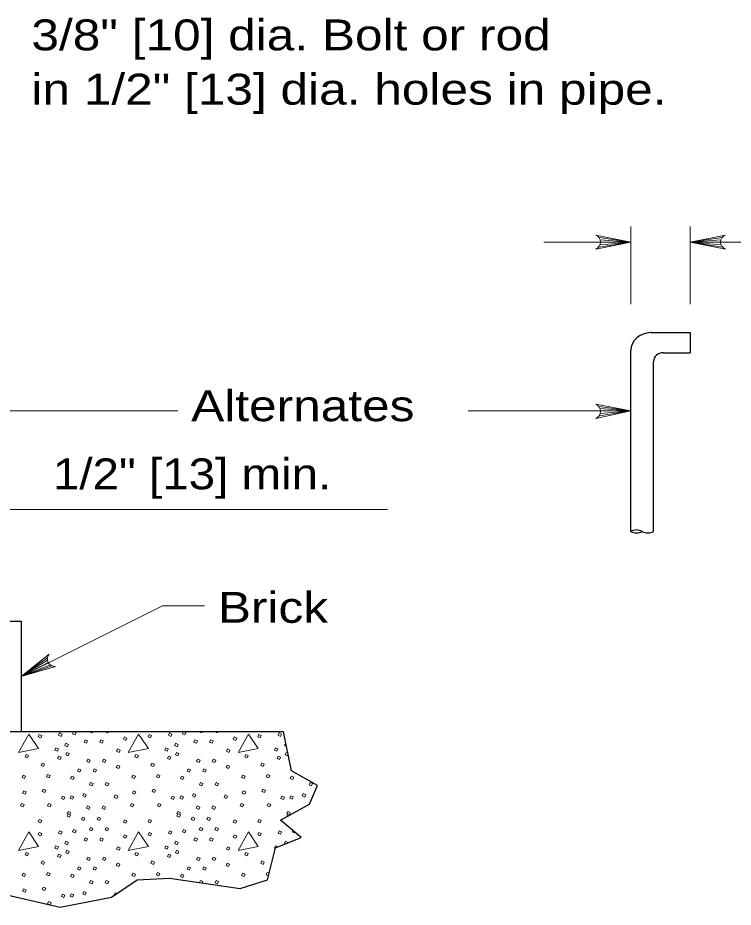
# Model space of a CAD drawing. Extents: x 1083.1 to 1117.1, y 697.4 to 741.4.
# Drawn here: x 1105.026 to 1108.637, y 729.063 to 733.552 of the extents above; entities that cross this region are included whole.
import ezdxf

# ---------------------------------------------------------------- set-up
doc = ezdxf.new("R2010")
doc.units = 0
doc.header["$LTSCALE"] = 0.062
doc.layers.add('1', color=7, linetype='Continuous', lineweight=13)

msp = doc.modelspace()

# ---------------------------------------------------------------- linework, layer by layer
at = {"layer": '1'}
for p, q in [((1108.12092, 732.10692), (1108.12092, 732.49875)), ((1108.42075, 732.10692), (1108.42075, 732.49875)), ((1107.68142, 732.42008), (1108.12092, 732.42008)), ((1107.95875, 732.39525), (1108.12092, 732.42008)), ((1107.96067, 732.4425), (1108.12092, 732.42008)), ((1107.96492, 732.40567), (1108.12092, 732.42008)), ((1107.96608, 732.43142), (1108.12092, 732.42008)), ((1107.96775, 732.42008), (1108.12092, 732.42008)), ((1108.581, 732.4425), (1108.42075, 732.42008)), ((1108.57558, 732.43142), (1108.42075, 732.42008)), ((1108.42075, 732.42008), (1109.891, 732.42008)), ((1108.57392, 732.42008), (1108.42075, 732.42008)), ((1108.57675, 732.40567), (1108.42075, 732.42008)), ((1108.58292, 732.39525), (1108.42075, 732.42008)), ((1108.22083, 731.963), (1108.22208, 731.963)), ((1104.49667, 731.56783), (1105.834, 731.56783)), ((1107.29892, 731.56783), (1108.12092, 731.56783)), ((1107.9585, 731.59092), (1108.12092, 731.56783)), ((1107.96092, 731.54375), (1108.12092, 731.56783)), ((1107.96475, 731.58058), (1108.12092, 731.56783)), ((1107.96625, 731.55492), (1108.12092, 731.56783)), ((1107.96775, 731.56625), (1108.12092, 731.56783)), ((1104.90975, 731.07075), (1106.89125, 731.07075)), ((1105.175, 730.32192), (1105.04333, 730.22792)), ((1105.17533, 730.30958), (1105.04333, 730.22792)), ((1105.17908, 730.29875), (1105.04333, 730.22792)), ((1105.18825, 730.28733), (1105.04333, 730.22792)), ((1105.1985, 730.28092), (1105.04333, 730.22792)), ((1106.377, 729.89042), (1106.37958, 729.88925)), ((1106.38125, 729.84483), (1106.38958, 729.84125)), ((1105.27467, 729.53533), (1105.27967, 729.54675)), ((1105.829, 729.53533), (1105.834, 729.54675)), ((1106.38333, 729.53533), (1106.38833, 729.54675)), ((1106.32667, 729.37325), (1106.33883, 729.368)), ((1106.285, 729.23917), (1106.29475, 729.23492)), ((1105.94275, 729.18775), (1105.94733, 729.19808)), ((1105.51267, 729.12408), (1105.5175, 729.13517)), ((1105.5175, 729.13517), (1105.52458, 729.13208))]:
    msp.add_line(p, q, dxfattribs=at)
at = {"layer": '1', "lineweight": 25}
for p, q in [((1108.22083, 731.963), (1108.42075, 731.963)), ((1108.42075, 731.963), (1108.42075, 731.86183)), ((1108.12092, 730.95983), (1108.12092, 731.87308)), ((1108.28508, 731.86183), (1108.42075, 731.86183)), ((1108.23517, 730.95983), (1108.23517, 731.81683)), ((1105.04333, 730.50717), (1105.04333, 729.94858))]:
    msp.add_line(p, q, dxfattribs=at)
at = {"layer": '1'}
for points in [[(1107.94392, 732.38467), (1108.12092, 732.42008), (1107.94392, 732.45542)], [(1108.59775, 732.38467), (1108.42075, 732.42008), (1108.59775, 732.45542)], [(1107.9435, 731.60142), (1108.12092, 731.56783), (1107.94425, 731.53058)], [(1105.04333, 730.22792), (1105.75608, 730.58458), (1105.9685, 730.58458)], [(1105.21658, 730.27842), (1105.04333, 730.22792), (1105.18383, 730.34117)], [(1105.31017, 729.94858), (1105.31983, 729.94442), (1105.31467, 729.93258), (1105.30217, 729.938), (1105.30683, 729.94858)], [(1105.40233, 729.94858), (1105.39967, 729.9425), (1105.38717, 729.94792), (1105.38742, 729.94858)], [(1105.4815, 729.94858), (1105.47883, 729.9425), (1105.46633, 729.94792), (1105.46667, 729.94858)], [(1105.8645, 729.94858), (1105.87417, 729.94442), (1105.869, 729.93258), (1105.8565, 729.938), (1105.86117, 729.94858)], [(1105.95667, 729.94858), (1105.954, 729.9425), (1105.9415, 729.94792), (1105.94175, 729.94858)], [(1106.03583, 729.94858), (1106.03317, 729.9425), (1106.02067, 729.94792), (1106.021, 729.94858)], [(1106.38275, 729.87383), (1106.37183, 729.87858), (1106.377, 729.89042)], [(1106.39117, 729.8335), (1106.38858, 729.82758), (1106.37608, 729.833), (1106.38125, 729.84483)], [(1105.27967, 729.54675), (1105.29217, 729.54133), (1105.28958, 729.53533)], [(1105.834, 729.54675), (1105.8465, 729.54133), (1105.84392, 729.53533)], [(1106.38683, 729.52192), (1106.38317, 729.5235), (1106.38833, 729.53533)], [(1106.38833, 729.54675), (1106.40083, 729.54133), (1106.39825, 729.53533)], [(1106.38833, 729.53533), (1106.40083, 729.52992), (1106.40067, 729.5295)], [(1106.42467, 729.44133), (1106.42333, 729.43817), (1106.41083, 729.44358), (1106.41383, 729.45033)], [(1106.326, 729.3595), (1106.3215, 729.36142), (1106.32667, 729.37325)], [(1106.3755, 729.3825), (1106.37183, 729.38408), (1106.377, 729.39592)], [(1106.377, 729.39592), (1106.3895, 729.3905), (1106.38817, 729.3875)], [(1106.29158, 729.22225), (1106.27983, 729.22733), (1106.285, 729.23917)], [(1105.94733, 729.19808), (1105.95983, 729.19267), (1105.95675, 729.18575)]]:
    msp.add_lwpolyline(points, dxfattribs=at)
at = {"layer": '1', "lineweight": 25}
for points in [[(1102.06542, 730.50717), (1104.80275, 730.50717), (1105.04333, 730.50717)], [(1106.36717, 729.94858), (1100.89558, 729.94858), (1100.89692, 729.84967)], [(1104.95458, 729.12908), (1105.23883, 729.06325), (1105.4985, 729.1145), (1105.62867, 729.20225), (1105.79083, 729.2095), (1106.14833, 729.15825), (1106.2865, 729.20225), (1106.327, 729.36333), (1106.45683, 729.41458), (1106.35125, 729.50233), (1106.49758, 729.583), (1106.53808, 729.678), (1106.40825, 729.75133), (1106.36717, 729.94858)]]:
    msp.add_lwpolyline(points, dxfattribs=at)
at = {"layer": '1'}
for points in [[(1105.23658, 729.94275), (1105.24908, 729.93733), (1105.24392, 729.9255), (1105.23142, 729.93092)], [(1105.79092, 729.94275), (1105.80333, 729.93733), (1105.79817, 729.9255), (1105.78575, 729.93092)], [(1106.34517, 729.94275), (1106.35767, 729.93733), (1106.3525, 729.9255), (1106.34, 729.93092)], [(1105.081, 729.93733), (1105.02875, 729.84475), (1105.131, 729.86475)], [(1105.13383, 729.93492), (1105.14633, 729.9295), (1105.14117, 729.91767), (1105.12867, 729.92308)], [(1105.36542, 729.908), (1105.37792, 729.90258), (1105.37275, 729.89083), (1105.36025, 729.89625)], [(1105.44458, 729.908), (1105.45708, 729.90258), (1105.45192, 729.89083), (1105.43942, 729.89625)], [(1105.564, 729.92267), (1105.5765, 729.91725), (1105.57133, 729.90542), (1105.55883, 729.91083)], [(1105.63525, 729.93733), (1105.58308, 729.84475), (1105.68533, 729.86475)], [(1105.68817, 729.93492), (1105.70067, 729.9295), (1105.6955, 729.91767), (1105.683, 729.92308)], [(1105.91975, 729.908), (1105.93225, 729.90258), (1105.92708, 729.89083), (1105.91458, 729.89625)], [(1105.99892, 729.908), (1106.01142, 729.90258), (1106.00625, 729.89083), (1105.99375, 729.89625)], [(1106.11833, 729.92267), (1106.13083, 729.91725), (1106.12567, 729.90542), (1106.11317, 729.91083)], [(1106.18958, 729.93733), (1106.13742, 729.84475), (1106.23967, 729.86475)], [(1106.2425, 729.93492), (1106.255, 729.9295), (1106.24983, 729.91767), (1106.23733, 729.92308)], [(1105.21808, 729.86775), (1105.23058, 729.86233), (1105.22542, 729.8505), (1105.21292, 729.85592)], [(1105.26833, 729.89042), (1105.28083, 729.885), (1105.27567, 729.87317), (1105.26325, 729.87858)], [(1105.52958, 729.86208), (1105.54208, 729.85667), (1105.53692, 729.84483), (1105.52442, 729.85025)], [(1105.77242, 729.86775), (1105.78492, 729.86233), (1105.77975, 729.8505), (1105.76725, 729.85592)], [(1105.82267, 729.89042), (1105.83517, 729.885), (1105.83, 729.87317), (1105.8175, 729.87858)], [(1106.08392, 729.86208), (1106.09642, 729.85667), (1106.09125, 729.84483), (1106.07875, 729.85025)], [(1106.32667, 729.86775), (1106.33917, 729.86233), (1106.334, 729.8505), (1106.3215, 729.85592)], [(1105.068, 729.83417), (1105.0805, 729.82875), (1105.07533, 729.81692), (1105.06283, 729.82233)], [(1105.23158, 729.82567), (1105.24408, 729.82025), (1105.23892, 729.80842), (1105.22642, 729.81383)], [(1105.27258, 729.84483), (1105.28508, 729.83942), (1105.27992, 729.82758), (1105.26742, 729.833)], [(1105.37883, 729.81083), (1105.39133, 729.80542), (1105.38617, 729.79358), (1105.37367, 729.799)], [(1105.458, 729.81083), (1105.4705, 729.80542), (1105.46533, 729.79358), (1105.45283, 729.799)], [(1105.62225, 729.83417), (1105.63475, 729.82875), (1105.62958, 729.81692), (1105.61708, 729.82233)], [(1105.78592, 729.82567), (1105.79833, 729.82025), (1105.79325, 729.80842), (1105.78075, 729.81383)], [(1105.82692, 729.84483), (1105.83942, 729.83942), (1105.83425, 729.82758), (1105.82175, 729.833)], [(1105.93317, 729.81083), (1105.94567, 729.80542), (1105.9405, 729.79358), (1105.928, 729.799)], [(1106.01233, 729.81083), (1106.02483, 729.80542), (1106.01967, 729.79358), (1106.00717, 729.799)], [(1106.17658, 729.83417), (1106.18908, 729.82875), (1106.18392, 729.81692), (1106.17142, 729.82233)], [(1106.34017, 729.82567), (1106.35267, 729.82025), (1106.3475, 729.80842), (1106.335, 729.81383)], [(1105.14867, 729.791), (1105.16117, 729.78558), (1105.156, 729.77375), (1105.1435, 729.77917)], [(1105.33142, 729.76125), (1105.34392, 729.75583), (1105.33875, 729.74408), (1105.32625, 729.7495)], [(1105.41067, 729.76125), (1105.42317, 729.75583), (1105.418, 729.74408), (1105.4055, 729.7495)], [(1105.52817, 729.78033), (1105.54067, 729.77492), (1105.5355, 729.76308), (1105.523, 729.7685)], [(1105.703, 729.791), (1105.7155, 729.78558), (1105.71033, 729.77375), (1105.69783, 729.77917)], [(1105.88575, 729.76125), (1105.89825, 729.75583), (1105.89308, 729.74408), (1105.88058, 729.7495)], [(1105.965, 729.76125), (1105.97742, 729.75583), (1105.97225, 729.74408), (1105.95983, 729.7495)], [(1106.0825, 729.78033), (1106.095, 729.77492), (1106.08983, 729.76308), (1106.07733, 729.7685)], [(1106.25733, 729.791), (1106.26983, 729.78558), (1106.26467, 729.77375), (1106.25217, 729.77917)], [(1105.05242, 729.73017), (1105.06492, 729.72475), (1105.05975, 729.71292), (1105.04725, 729.71833)], [(1105.17633, 729.73367), (1105.18883, 729.72825), (1105.18367, 729.71642), (1105.17117, 729.72183)], [(1105.29742, 729.72517), (1105.30992, 729.71975), (1105.30475, 729.70792), (1105.29225, 729.71333)], [(1105.60675, 729.73017), (1105.61917, 729.72475), (1105.61408, 729.71292), (1105.60158, 729.71833)], [(1105.73067, 729.73367), (1105.74317, 729.72825), (1105.738, 729.71642), (1105.7255, 729.72183)], [(1105.85175, 729.72517), (1105.86425, 729.71975), (1105.85908, 729.70792), (1105.84658, 729.71333)], [(1106.161, 729.73017), (1106.1735, 729.72475), (1106.16833, 729.71292), (1106.15583, 729.71833)], [(1106.285, 729.73367), (1106.2975, 729.72825), (1106.29233, 729.71642), (1106.27983, 729.72183)], [(1106.40608, 729.72517), (1106.41858, 729.71975), (1106.41342, 729.70792), (1106.40092, 729.71333)], [(1105.393, 729.69258), (1105.4055, 729.68717), (1105.40033, 729.67533), (1105.38783, 729.68075)], [(1105.47217, 729.69258), (1105.48467, 729.68717), (1105.4795, 729.67533), (1105.467, 729.68075)], [(1105.94733, 729.69258), (1105.95983, 729.68717), (1105.95467, 729.67533), (1105.94217, 729.68075)], [(1106.0265, 729.69258), (1106.039, 729.68717), (1106.03383, 729.67533), (1106.02133, 729.68075)], [(1106.50158, 729.69258), (1106.51408, 729.68717), (1106.50892, 729.67533), (1106.4965, 729.68075)], [(1105.05533, 729.651), (1105.06783, 729.64558), (1105.06267, 729.63375), (1105.05017, 729.63917)], [(1105.15433, 729.65933), (1105.16683, 729.65392), (1105.16167, 729.64208), (1105.14917, 729.6475)], [(1105.25075, 729.62392), (1105.26325, 729.6185), (1105.25808, 729.60675), (1105.24558, 729.61208)], [(1105.29525, 729.626), (1105.30775, 729.62058), (1105.30258, 729.60883), (1105.29008, 729.61417)], [(1105.35833, 729.63667), (1105.37083, 729.63125), (1105.36567, 729.61942), (1105.35317, 729.62483)], [(1105.5175, 729.62958), (1105.53, 729.62417), (1105.52483, 729.61242), (1105.51233, 729.61775)], [(1105.60967, 729.651), (1105.62208, 729.64558), (1105.61692, 729.63375), (1105.6045, 729.63917)], [(1105.70867, 729.65933), (1105.72117, 729.65392), (1105.716, 729.64208), (1105.7035, 729.6475)], [(1105.805, 729.62392), (1105.8175, 729.6185), (1105.81233, 729.60675), (1105.79983, 729.61208)], [(1105.84958, 729.626), (1105.86208, 729.62058), (1105.85692, 729.60883), (1105.84442, 729.61417)], [(1105.91267, 729.63667), (1105.92517, 729.63125), (1105.92, 729.61942), (1105.9075, 729.62483)], [(1106.07183, 729.62958), (1106.08433, 729.62417), (1106.07917, 729.61242), (1106.06667, 729.61775)], [(1106.16392, 729.651), (1106.17642, 729.64558), (1106.17125, 729.63375), (1106.15875, 729.63917)], [(1106.263, 729.65933), (1106.2755, 729.65392), (1106.27033, 729.64208), (1106.25783, 729.6475)], [(1106.35933, 729.62392), (1106.37183, 729.6185), (1106.36667, 729.60675), (1106.35417, 729.61208)], [(1106.40392, 729.626), (1106.41642, 729.62058), (1106.41125, 729.60883), (1106.39875, 729.61417)], [(1106.467, 729.63667), (1106.4795, 729.63125), (1106.47433, 729.61942), (1106.46183, 729.62483)], [(1105.04492, 729.58692), (1105.05742, 729.5815), (1105.05225, 729.56967), (1105.03975, 729.57508)], [(1105.18125, 729.58717), (1105.19375, 729.58175), (1105.18858, 729.56992), (1105.17608, 729.57533)], [(1105.59925, 729.58692), (1105.61175, 729.5815), (1105.60658, 729.56967), (1105.59408, 729.57508)], [(1105.73558, 729.58717), (1105.74808, 729.58175), (1105.74292, 729.56992), (1105.73042, 729.57533)], [(1106.1535, 729.58692), (1106.166, 729.5815), (1106.16083, 729.56967), (1106.14833, 729.57508)], [(1106.28992, 729.58717), (1106.30242, 729.58175), (1106.29725, 729.56992), (1106.28475, 729.57533)], [(1105.27967, 729.53533), (1105.29217, 729.52992), (1105.287, 729.51808), (1105.2745, 729.5235)], [(1105.37742, 729.57442), (1105.38992, 729.569), (1105.38475, 729.55717), (1105.37225, 729.56258)], [(1105.45658, 729.57442), (1105.46908, 729.569), (1105.46392, 729.55717), (1105.45142, 729.56258)], [(1105.834, 729.53533), (1105.8465, 729.52992), (1105.84133, 729.51808), (1105.82883, 729.5235)], [(1105.93175, 729.57442), (1105.94425, 729.569), (1105.93908, 729.55717), (1105.92658, 729.56258)], [(1106.01092, 729.57442), (1106.02342, 729.569), (1106.01825, 729.55717), (1106.00575, 729.56258)], [(1105.13383, 729.50558), (1105.14633, 729.50017), (1105.14117, 729.48833), (1105.12867, 729.49375)], [(1105.35192, 729.51833), (1105.36442, 729.51292), (1105.35925, 729.50108), (1105.34675, 729.5065)], [(1105.43117, 729.51833), (1105.44358, 729.51292), (1105.4385, 729.50108), (1105.426, 729.5065)], [(1105.56425, 729.50492), (1105.57675, 729.4995), (1105.57158, 729.48767), (1105.55908, 729.49308)], [(1105.68817, 729.50558), (1105.70067, 729.50017), (1105.6955, 729.48833), (1105.683, 729.49375)], [(1105.90625, 729.51833), (1105.91875, 729.51292), (1105.91358, 729.50108), (1105.90108, 729.5065)], [(1105.98542, 729.51833), (1105.99792, 729.51292), (1105.99275, 729.50108), (1105.98025, 729.5065)], [(1106.11858, 729.50492), (1106.13108, 729.4995), (1106.12592, 729.48767), (1106.11342, 729.49308)], [(1106.2425, 729.50558), (1106.255, 729.50017), (1106.24983, 729.48833), (1106.23733, 729.49375)], [(1105.23658, 729.44833), (1105.24908, 729.44292), (1105.24392, 729.43108), (1105.23142, 729.4365)], [(1105.30733, 729.45542), (1105.31983, 729.45), (1105.31467, 729.43817), (1105.30217, 729.44358)], [(1105.39233, 729.46533), (1105.40483, 729.45992), (1105.39967, 729.44808), (1105.38717, 729.4535)], [(1105.4715, 729.46533), (1105.484, 729.45992), (1105.47883, 729.44808), (1105.46633, 729.4535)], [(1105.79092, 729.44833), (1105.80333, 729.44292), (1105.79817, 729.43108), (1105.78575, 729.4365)], [(1105.86167, 729.45542), (1105.87417, 729.45), (1105.869, 729.43817), (1105.8565, 729.44358)], [(1105.94667, 729.46533), (1105.95917, 729.45992), (1105.954, 729.44808), (1105.9415, 729.4535)], [(1106.02583, 729.46533), (1106.03833, 729.45992), (1106.03317, 729.44808), (1106.02067, 729.4535)], [(1106.34517, 729.44833), (1106.35767, 729.44292), (1106.3525, 729.43108), (1106.34, 729.4365)], [(1105.081, 729.44292), (1105.02875, 729.35025), (1105.131, 729.37025)], [(1105.13383, 729.4405), (1105.14633, 729.43508), (1105.14117, 729.42325), (1105.12867, 729.42867)], [(1105.36542, 729.41358), (1105.37792, 729.40817), (1105.37275, 729.39633), (1105.36025, 729.40175)], [(1105.44458, 729.41358), (1105.45708, 729.40817), (1105.45192, 729.39633), (1105.43942, 729.40175)], [(1105.564, 729.42825), (1105.5765, 729.42283), (1105.57133, 729.411), (1105.55883, 729.41642)], [(1105.63525, 729.44292), (1105.58308, 729.35025), (1105.68533, 729.37025)], [(1105.68817, 729.4405), (1105.70067, 729.43508), (1105.6955, 729.42325), (1105.683, 729.42867)], [(1105.91975, 729.41358), (1105.93225, 729.40817), (1105.92708, 729.39633), (1105.91458, 729.40175)], [(1105.99892, 729.41358), (1106.01142, 729.40817), (1106.00625, 729.39633), (1105.99375, 729.40175)], [(1106.11833, 729.42825), (1106.13083, 729.42283), (1106.12567, 729.411), (1106.11317, 729.41642)], [(1106.18958, 729.44292), (1106.13742, 729.35025), (1106.23967, 729.37025)], [(1106.2425, 729.4405), (1106.255, 729.43508), (1106.24983, 729.42325), (1106.23733, 729.42867)], [(1105.21808, 729.37325), (1105.23058, 729.36783), (1105.22542, 729.356), (1105.21292, 729.36142)], [(1105.26833, 729.39592), (1105.28083, 729.3905), (1105.27567, 729.37867), (1105.26325, 729.38408)], [(1105.52958, 729.36758), (1105.54208, 729.36217), (1105.53692, 729.35033), (1105.52442, 729.35575)], [(1105.77242, 729.37325), (1105.78492, 729.36783), (1105.77975, 729.356), (1105.76725, 729.36142)], [(1105.82267, 729.39592), (1105.83517, 729.3905), (1105.83, 729.37867), (1105.8175, 729.38408)], [(1106.08392, 729.36758), (1106.09642, 729.36217), (1106.09125, 729.35033), (1106.07875, 729.35575)], [(1105.068, 729.33967), (1105.0805, 729.33425), (1105.07533, 729.3225), (1105.06283, 729.32783)], [(1105.23158, 729.33117), (1105.24408, 729.32583), (1105.23892, 729.314), (1105.22642, 729.31942)], [(1105.27258, 729.35033), (1105.28508, 729.34492), (1105.27992, 729.33308), (1105.26742, 729.3385)], [(1105.37883, 729.31642), (1105.39133, 729.311), (1105.38617, 729.29917), (1105.37367, 729.30458)], [(1105.458, 729.31642), (1105.4705, 729.311), (1105.46533, 729.29917), (1105.45283, 729.30458)], [(1105.62225, 729.33967), (1105.63475, 729.33425), (1105.62958, 729.3225), (1105.61708, 729.32783)], [(1105.78592, 729.33117), (1105.79833, 729.32583), (1105.79325, 729.314), (1105.78075, 729.31942)], [(1105.82692, 729.35033), (1105.83942, 729.34492), (1105.83425, 729.33308), (1105.82175, 729.3385)], [(1105.93317, 729.31642), (1105.94567, 729.311), (1105.9405, 729.29917), (1105.928, 729.30458)], [(1106.01233, 729.31642), (1106.02483, 729.311), (1106.01967, 729.29917), (1106.00717, 729.30458)], [(1106.17658, 729.33967), (1106.18908, 729.33425), (1106.18392, 729.3225), (1106.17142, 729.32783)], [(1105.14867, 729.29658), (1105.16117, 729.29117), (1105.156, 729.27933), (1105.1435, 729.28475)], [(1105.33142, 729.26683), (1105.34392, 729.26142), (1105.33875, 729.24958), (1105.32625, 729.255)], [(1105.41067, 729.26683), (1105.42317, 729.26142), (1105.418, 729.24958), (1105.4055, 729.255)], [(1105.52817, 729.28592), (1105.54067, 729.2805), (1105.5355, 729.26867), (1105.523, 729.27408)], [(1105.703, 729.29658), (1105.7155, 729.29117), (1105.71033, 729.27933), (1105.69783, 729.28475)], [(1105.88575, 729.26683), (1105.89825, 729.26142), (1105.89308, 729.24958), (1105.88058, 729.255)], [(1105.965, 729.26683), (1105.97742, 729.26142), (1105.97225, 729.24958), (1105.95983, 729.255)], [(1106.0825, 729.28592), (1106.095, 729.2805), (1106.08983, 729.26867), (1106.07733, 729.27408)], [(1106.25733, 729.29658), (1106.26983, 729.29117), (1106.26467, 729.27933), (1106.25217, 729.28475)], [(1105.05242, 729.23567), (1105.06492, 729.23025), (1105.05975, 729.21842), (1105.04725, 729.22383)], [(1105.17633, 729.23917), (1105.18883, 729.23375), (1105.18367, 729.22192), (1105.17117, 729.22733)], [(1105.29742, 729.23067), (1105.30992, 729.22525), (1105.30475, 729.21342), (1105.29225, 729.21883)], [(1105.60675, 729.23567), (1105.61917, 729.23025), (1105.61408, 729.21842), (1105.60158, 729.22383)], [(1105.73067, 729.23917), (1105.74317, 729.23375), (1105.738, 729.22192), (1105.7255, 729.22733)], [(1105.85175, 729.23067), (1105.86425, 729.22525), (1105.85908, 729.21342), (1105.84658, 729.21883)], [(1106.161, 729.23567), (1106.1735, 729.23025), (1106.16833, 729.21842), (1106.15583, 729.22383)], [(1105.393, 729.19808), (1105.4055, 729.19267), (1105.40033, 729.18092), (1105.38783, 729.18625)], [(1105.47217, 729.19808), (1105.48467, 729.19267), (1105.4795, 729.18092), (1105.467, 729.18625)], [(1106.0265, 729.19808), (1106.039, 729.19267), (1106.03383, 729.18092), (1106.02133, 729.18625)], [(1105.05533, 729.15658), (1105.06783, 729.15117), (1105.06267, 729.13933), (1105.05017, 729.14475)], [(1105.15433, 729.16492), (1105.16683, 729.1595), (1105.16167, 729.14767), (1105.14917, 729.15308)], [(1105.25075, 729.1295), (1105.26325, 729.12408), (1105.25808, 729.11225), (1105.24558, 729.11767)], [(1105.29525, 729.13158), (1105.30775, 729.12617), (1105.30258, 729.11433), (1105.29008, 729.11975)], [(1105.35833, 729.14225), (1105.37083, 729.13683), (1105.36567, 729.125), (1105.35317, 729.13042)], [(1105.18125, 729.09267), (1105.19375, 729.08725), (1105.18858, 729.07542), (1105.17608, 729.08083)]]:
    msp.add_lwpolyline(points, close=True, dxfattribs=at)
for centre, start, end in [((1107.9296, 732.42009), 292.08605, 67.91218), ((1108.61205, 732.42009), 112.08782, 247.91395), ((1107.92962, 731.56581), 292.69411, 68.52023), ((1105.21289, 730.31643), 139.64053, 275.46666)]:
    msp.add_arc(centre, 0.0382, start, end, dxfattribs=at)
at = {"layer": '1', "lineweight": 25}
for centre, major_axis, start_param, end_param in [((1108.22085, 731.87308), (-0.09995, 0), 4.712389, 6.2831853), ((1108.28512, 731.81687), (-0.04998, 0), 4.712389, 6.2831853), ((1108.14949, 730.91758), (-0.05498, 0), 4.1655638, 5.2592141), ((1108.14949, 731.0021), (-0.05498, 0), 1.0239712, 2.1176215), ((1108.20661, 731.00263), (-0.05545, 0), 1.0302438, 2.1113489)]:
    msp.add_ellipse(centre, major_axis=major_axis, ratio=0.899905, start_param=start_param, end_param=end_param, dxfattribs=at)

# ---------------------------------------------------------------- texts
at = {"layer": '1'}
for s, width, p in [('3/8" [10] dia. Bolt or rod', 1.2, (1105.09433, 733.38783)), ('in 1/2" [13] dia. holes in pipe.', 1.2, (1105.09433, 733.11383)), ('Alternates', 1.2, (1105.901, 731.51625)), ('1/2" [13] min.', 1.15, (1105.20283, 731.17217)), ('Brick', 1.2, (1106.03567, 730.4985))]:
    msp.add_text(s, height=0.156, dxfattribs=dict(at, width=width)).set_placement(p)

doc.saveas('drawing.dxf')
